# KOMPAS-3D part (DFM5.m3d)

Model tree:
1. Эскиз:1
2. Операция выдавливания:1
     Расстояние 1 = 3
3. Эскиз:2
4. Операция выдавливания:2
     Расстояние 1 = 3
5. Фаска:1
     Угол = 40; Длина 1 = 0.8; Длина 2 = 0.67128
